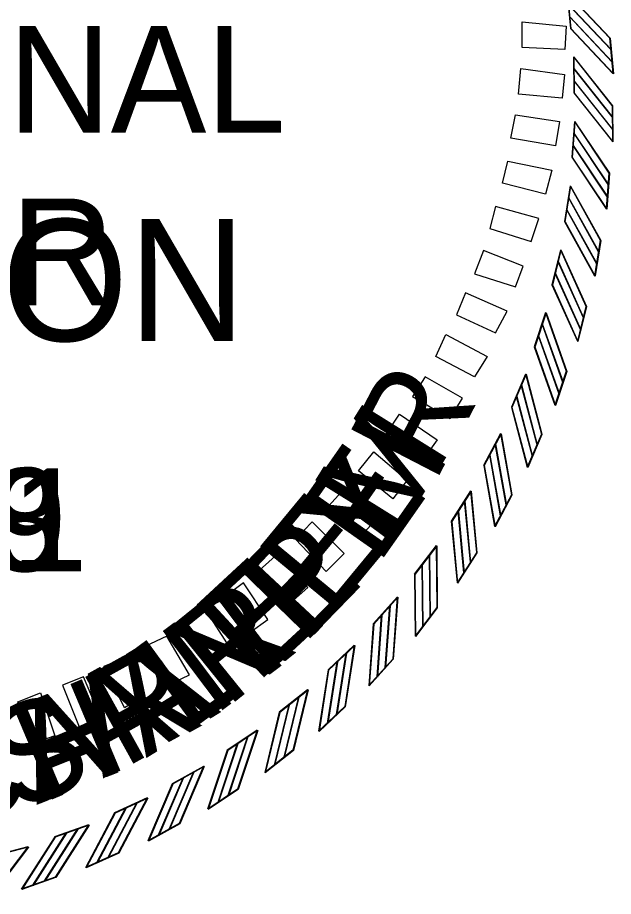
# Model space of a CAD drawing. Extents: x 16 to 1228740, y 11 to 152440.
# Drawn here: x 17.7889 to 17.8514, y 10.8175 to 10.9098 of the extents above; entities that cross this region are included whole.
import ezdxf

# ---------------------------------------------------------------- set-up
doc = ezdxf.new("R2010")
doc.units = 0
for name, color, linetype in [('STAMP_FRED', 7, 'Continuous'), ('STAMP_HUSSAM', 7, 'Continuous'), ('STAMP_JUSTIN', 7, 'Continuous'), ('STAMP_PRELIM', 7, 'Continuous')]:
    doc.layers.add(name, color=color, linetype=linetype)

msp = doc.modelspace()

# ---------------------------------------------------------------- linework, layer by layer
at = {"layer": 'STAMP_FRED'}
for p, q in [((17.84661, 10.912405), (17.846957, 10.908642)), ((17.851077, 10.90765), (17.851423, 10.903896)), ((17.847275, 10.905655), (17.84731, 10.901877)), ((17.851334, 10.900548), (17.851369, 10.896778)), ((17.847381, 10.898874), (17.847104, 10.895106)), ((17.851004, 10.893449), (17.850727, 10.889689)), ((17.846926, 10.892108), (17.846339, 10.888375)), ((17.850089, 10.886402), (17.849503, 10.882678)), ((17.845915, 10.885402), (17.845021, 10.88173)), ((17.844352, 10.878802), (17.843158, 10.875217)), ((17.848595, 10.879454), (17.847704, 10.875791)), ((17.842251, 10.872354), (17.840765, 10.86888)), ((17.846533, 10.872653), (17.845342, 10.869077)), ((17.839623, 10.866102), (17.837856, 10.862762)), ((17.843916, 10.866046), (17.842433, 10.86258)), ((17.836489, 10.860087), (17.834451, 10.856905)), ((17.840762, 10.859678), (17.838999, 10.856346)), ((17.832869, 10.854353), (17.830575, 10.85135)), ((17.837093, 10.853592), (17.835061, 10.850417)), ((17.828787, 10.848937), (17.826253, 10.846133)), ((17.832935, 10.847829), (17.830646, 10.844833)), ((17.824272, 10.843876), (17.821516, 10.841291)), ((17.828314, 10.84243), (17.825786, 10.839633)), ((17.819355, 10.839205), (17.816394, 10.836857)), ((17.823263, 10.83743), (17.820513, 10.834852)), ((17.814068, 10.834957), (17.810924, 10.832861)), ((17.817817, 10.832865), (17.814864, 10.830522)), ((17.808449, 10.831159), (17.805143, 10.829331)), ((17.812013, 10.828765), (17.808876, 10.826674)), ((17.802536, 10.827839), (17.799089, 10.826289)), ((17.796368, 10.825018), (17.792806, 10.823758)), ((17.805889, 10.825159), (17.80259, 10.823334)), ((17.789989, 10.822716), (17.786335, 10.821755)), ((17.799489, 10.82207), (17.796051, 10.820524)), ((17.792855, 10.819521), (17.789301, 10.818264))]:
    msp.add_line(p, q, dxfattribs=at)
for points in [[(17.846606, 10.912409), (17.851073, 10.907655)], [(17.846706, 10.9112), (17.851173, 10.906446)], [(17.846855, 10.909898), (17.851322, 10.905144)], [(17.846959, 10.908647), (17.851426, 10.903893)], [(17.847272, 10.90566), (17.851331, 10.900553)], [(17.847272, 10.904447), (17.851331, 10.89934)], [(17.847313, 10.903137), (17.851372, 10.898031)], [(17.847313, 10.901881), (17.851372, 10.896775)], [(17.847378, 10.898879), (17.851001, 10.893455)], [(17.847278, 10.89767), (17.850901, 10.892245)], [(17.84721, 10.896362), (17.850834, 10.890937)], [(17.847107, 10.89511), (17.85073, 10.889686)], [(17.846924, 10.892113), (17.850087, 10.886408)], [(17.846724, 10.890916), (17.849887, 10.885211)], [(17.846549, 10.889618), (17.849712, 10.883913)], [(17.846342, 10.888379), (17.849505, 10.882674)], [(17.845912, 10.885407), (17.848593, 10.87946)], [(17.845614, 10.884231), (17.848295, 10.878284)], [(17.845333, 10.882951), (17.848014, 10.877005)], [(17.845024, 10.881734), (17.847705, 10.875787)], [(17.84435, 10.878807), (17.846531, 10.87266)], [(17.843956, 10.87766), (17.846137, 10.871512)], [(17.84357, 10.876408), (17.845751, 10.87026)], [(17.843162, 10.87522), (17.845343, 10.869072)], [(17.842249, 10.87236), (17.843915, 10.866053)], [(17.841762, 10.871248), (17.843427, 10.864941)], [(17.841273, 10.870033), (17.842939, 10.863726)], [(17.840769, 10.868883), (17.842434, 10.862576)], [(17.839622, 10.866107), (17.840762, 10.859684)], [(17.839045, 10.86504), (17.840184, 10.858617)], [(17.838458, 10.863869), (17.839597, 10.857446)], [(17.83786, 10.862765), (17.838999, 10.856342)], [(17.836488, 10.860093), (17.837093, 10.853598)], [(17.835825, 10.859077), (17.83643, 10.852582)], [(17.835143, 10.857959), (17.835748, 10.851464)], [(17.834456, 10.856907), (17.835061, 10.850412)], [(17.832869, 10.854358), (17.832935, 10.847836)], [(17.832123, 10.853401), (17.83219, 10.846878)], [(17.831351, 10.852343), (17.831418, 10.84582)], [(17.83058, 10.851351), (17.830646, 10.844829)], [(17.828787, 10.848942), (17.828315, 10.842436)], [(17.827966, 10.84805), (17.827493, 10.841543)], [(17.827109, 10.847059), (17.826637, 10.840552)], [(17.826258, 10.846134), (17.825786, 10.839628)], [(17.824273, 10.843882), (17.823265, 10.837437)], [(17.82338, 10.84306), (17.822372, 10.836615)], [(17.822445, 10.842143), (17.821437, 10.835698)], [(17.821521, 10.841292), (17.820513, 10.834847)], [(17.819356, 10.839211), (17.817819, 10.832871)], [(17.818398, 10.838466), (17.816862, 10.832126)], [(17.81739, 10.837629), (17.815854, 10.83129)], [(17.816399, 10.836858), (17.814862, 10.830518)], [(17.813054, 10.834299), (17.810999, 10.828108)], [(17.81407, 10.834962), (17.812015, 10.828771)], [(17.811981, 10.833548), (17.809926, 10.827357)], [(17.810929, 10.832861), (17.808874, 10.82667)], [(17.807384, 10.830587), (17.804825, 10.824587)], [(17.808452, 10.831165), (17.805892, 10.825165)], [(17.806252, 10.829928), (17.803693, 10.823928)], [(17.805148, 10.82933), (17.802589, 10.82333)], [(17.802538, 10.827844), (17.799492, 10.822076)], [(17.801427, 10.827357), (17.798381, 10.821588)], [(17.799095, 10.826289), (17.796048, 10.82052)], [(17.800245, 10.826793), (17.797199, 10.821025)], [(17.796371, 10.825023), (17.792859, 10.819526)], [(17.793999, 10.824165), (17.790487, 10.818668)], [(17.795224, 10.824629), (17.791712, 10.819132)], [(17.792811, 10.823757), (17.789299, 10.81826)], [(17.789992, 10.822721), (17.786038, 10.817533)]]:
    msp.add_lwpolyline(points, dxfattribs=at)
at = {"layer": 'STAMP_HUSSAM'}
for p, q in [((17.846554, 10.912435), (17.846901, 10.908673)), ((17.851021, 10.907681), (17.851367, 10.903927)), ((17.847219, 10.905686), (17.847254, 10.901908)), ((17.851278, 10.900579), (17.851313, 10.896809)), ((17.847325, 10.898905), (17.847048, 10.895137)), ((17.850948, 10.89348), (17.850672, 10.88972)), ((17.846871, 10.892138), (17.846283, 10.888406)), ((17.850033, 10.886433), (17.849447, 10.882708)), ((17.845859, 10.885432), (17.844965, 10.881761)), ((17.84854, 10.879485), (17.847648, 10.875822)), ((17.844297, 10.878833), (17.843103, 10.875248)), ((17.842195, 10.872385), (17.840709, 10.868911)), ((17.846477, 10.872684), (17.845286, 10.869107)), ((17.839568, 10.866132), (17.8378, 10.862793)), ((17.84386, 10.866077), (17.842378, 10.862611)), ((17.836433, 10.860118), (17.834396, 10.856936)), ((17.840706, 10.859709), (17.838943, 10.856377)), ((17.832813, 10.854384), (17.830519, 10.85138)), ((17.837038, 10.853622), (17.835005, 10.850448)), ((17.828731, 10.848967), (17.826198, 10.846164)), ((17.832879, 10.84786), (17.830591, 10.844864)), ((17.824216, 10.843907), (17.82146, 10.841322)), ((17.828258, 10.842461), (17.825731, 10.839664)), ((17.819299, 10.839236), (17.816338, 10.836888)), ((17.823208, 10.837461), (17.820458, 10.834883)), ((17.814013, 10.834988), (17.810868, 10.832892)), ((17.817761, 10.832896), (17.814808, 10.830553)), ((17.808393, 10.83119), (17.805087, 10.829361)), ((17.811957, 10.828796), (17.80882, 10.826705)), ((17.80248, 10.82787), (17.799034, 10.82632)), ((17.796313, 10.825049), (17.79275, 10.823789)), ((17.805833, 10.82519), (17.802534, 10.823365)), ((17.789933, 10.822747), (17.786279, 10.821786)), ((17.799433, 10.822101), (17.795995, 10.820555)), ((17.7928, 10.819552), (17.789245, 10.818295))]:
    msp.add_line(p, q, dxfattribs=at)
for points in [[(17.84655, 10.91244), (17.851017, 10.907686)], [(17.84665, 10.91123), (17.851117, 10.906476)], [(17.846799, 10.909929), (17.851266, 10.905175)], [(17.846903, 10.908677), (17.85137, 10.903923)], [(17.847216, 10.905691), (17.851275, 10.900584)], [(17.847216, 10.904477), (17.851275, 10.899371)], [(17.847257, 10.903168), (17.851316, 10.898061)], [(17.847257, 10.901912), (17.851316, 10.896806)], [(17.847322, 10.89891), (17.850945, 10.893486)], [(17.847222, 10.897701), (17.850845, 10.892276)], [(17.847155, 10.896392), (17.850778, 10.890968)], [(17.847051, 10.895141), (17.850674, 10.889716)], [(17.846868, 10.892144), (17.850031, 10.886438)], [(17.846668, 10.890947), (17.849831, 10.885242)], [(17.846493, 10.889648), (17.849656, 10.883943)], [(17.846286, 10.88841), (17.849449, 10.882705)], [(17.845856, 10.885438), (17.848537, 10.879491)], [(17.845559, 10.884261), (17.84824, 10.878315)], [(17.845277, 10.882982), (17.847958, 10.877035)], [(17.844969, 10.881765), (17.84765, 10.875818)], [(17.844295, 10.878838), (17.846476, 10.87269)], [(17.843901, 10.877691), (17.846082, 10.871543)], [(17.843514, 10.876439), (17.845695, 10.870291)], [(17.843107, 10.875251), (17.845287, 10.869103)], [(17.842193, 10.87239), (17.843859, 10.866083)], [(17.841706, 10.871279), (17.843372, 10.864972)], [(17.841218, 10.870064), (17.842883, 10.863757)], [(17.840713, 10.868914), (17.842379, 10.862607)], [(17.839567, 10.866138), (17.840706, 10.859715)], [(17.838989, 10.865071), (17.840128, 10.858648)], [(17.838402, 10.8639), (17.839541, 10.857477)], [(17.837804, 10.862795), (17.838943, 10.856372)], [(17.836433, 10.860124), (17.837038, 10.853629)], [(17.835769, 10.859108), (17.836374, 10.852613)], [(17.835087, 10.85799), (17.835692, 10.851495)], [(17.8344, 10.856938), (17.835005, 10.850443)], [(17.832813, 10.854389), (17.832879, 10.847866)], [(17.832067, 10.853432), (17.832134, 10.846909)], [(17.831296, 10.852373), (17.831362, 10.845851)], [(17.830524, 10.851382), (17.830591, 10.844859)], [(17.82791, 10.84808), (17.827437, 10.841574)], [(17.828732, 10.848973), (17.828259, 10.842467)], [(17.827053, 10.847089), (17.826581, 10.840583)], [(17.826203, 10.846165), (17.82573, 10.839659)], [(17.824217, 10.843912), (17.823209, 10.837468)], [(17.823324, 10.843091), (17.822316, 10.836646)], [(17.822389, 10.842174), (17.821381, 10.835729)], [(17.821465, 10.841323), (17.820457, 10.834878)], [(17.8193, 10.839242), (17.817763, 10.832902)], [(17.818343, 10.838497), (17.816806, 10.832157)], [(17.817335, 10.83766), (17.815798, 10.83132)], [(17.816344, 10.836889), (17.814807, 10.830549)], [(17.812999, 10.83433), (17.810943, 10.828139)], [(17.814014, 10.834993), (17.811959, 10.828802)], [(17.811925, 10.833579), (17.80987, 10.827388)], [(17.810873, 10.832892), (17.808818, 10.826701)], [(17.807329, 10.830618), (17.804769, 10.824618)], [(17.808396, 10.831196), (17.805836, 10.825195)], [(17.806197, 10.829959), (17.803637, 10.823959)], [(17.805092, 10.829361), (17.802533, 10.823361)], [(17.802483, 10.827875), (17.799437, 10.822107)], [(17.801371, 10.827388), (17.798325, 10.821619)], [(17.799039, 10.82632), (17.795993, 10.820551)], [(17.800189, 10.826824), (17.797143, 10.821056)], [(17.796316, 10.825054), (17.792804, 10.819557)], [(17.793943, 10.824196), (17.790431, 10.818699)], [(17.795168, 10.82466), (17.791656, 10.819163)], [(17.792755, 10.823788), (17.789243, 10.818291)], [(17.789937, 10.822752), (17.785983, 10.817564)]]:
    msp.add_lwpolyline(points, dxfattribs=at)
at = {"layer": 'STAMP_JUSTIN'}
for p, q in [((17.846608, 10.912405), (17.846954, 10.908643)), ((17.851075, 10.907651), (17.85142, 10.903897)), ((17.847273, 10.905656), (17.847308, 10.901878)), ((17.851332, 10.900549), (17.851367, 10.896779)), ((17.847379, 10.898875), (17.847102, 10.895107)), ((17.851002, 10.89345), (17.850725, 10.889691)), ((17.846924, 10.892109), (17.846337, 10.888376)), ((17.850087, 10.886403), (17.849501, 10.882679)), ((17.845912, 10.885403), (17.845019, 10.881732)), ((17.848593, 10.879455), (17.847701, 10.875793)), ((17.84435, 10.878804), (17.843156, 10.875219)), ((17.842249, 10.872356), (17.840763, 10.868881)), ((17.846531, 10.872655), (17.84534, 10.869078)), ((17.839622, 10.866103), (17.837854, 10.862764)), ((17.843914, 10.866048), (17.842431, 10.862582)), ((17.836487, 10.860089), (17.83445, 10.856907)), ((17.84076, 10.85968), (17.838997, 10.856348)), ((17.832867, 10.854355), (17.830574, 10.851352)), ((17.837092, 10.853594), (17.835059, 10.850419)), ((17.828785, 10.848939), (17.826252, 10.846135)), ((17.832933, 10.847831), (17.830645, 10.844835)), ((17.824271, 10.843878), (17.821514, 10.841294)), ((17.828312, 10.842432), (17.825785, 10.839635)), ((17.819353, 10.839208), (17.816393, 10.83686)), ((17.823262, 10.837433), (17.820512, 10.834854)), ((17.814067, 10.834959), (17.810923, 10.832864)), ((17.817816, 10.832868), (17.814862, 10.830525)), ((17.808448, 10.831162), (17.805142, 10.829333)), ((17.812011, 10.828768), (17.808874, 10.826677)), ((17.802535, 10.827842), (17.799089, 10.826292)), ((17.796367, 10.825021), (17.792805, 10.823761)), ((17.805888, 10.825162), (17.802589, 10.823337)), ((17.789988, 10.822719), (17.786334, 10.821758)), ((17.799488, 10.822073), (17.79605, 10.820527)), ((17.792855, 10.819524), (17.7893, 10.818267))]:
    msp.add_line(p, q, dxfattribs=at)
for points in [[(17.846604, 10.91241), (17.851071, 10.907656)], [(17.846704, 10.9112), (17.851171, 10.906446)], [(17.846853, 10.909899), (17.85132, 10.905145)], [(17.846957, 10.908647), (17.851423, 10.903893)], [(17.84727, 10.905661), (17.851328, 10.900554)], [(17.84727, 10.904447), (17.851328, 10.899341)], [(17.847311, 10.903138), (17.851369, 10.898032)], [(17.847311, 10.901882), (17.851369, 10.896776)], [(17.847376, 10.89888), (17.850999, 10.893456)], [(17.847276, 10.897671), (17.850899, 10.892247)], [(17.847208, 10.896363), (17.850831, 10.890938)], [(17.847105, 10.895111), (17.850728, 10.889687)], [(17.846922, 10.892114), (17.850084, 10.886409)], [(17.846722, 10.890917), (17.849885, 10.885212)], [(17.846547, 10.889619), (17.84971, 10.883914)], [(17.84634, 10.88838), (17.849503, 10.882675)], [(17.84591, 10.885408), (17.848591, 10.879462)], [(17.845612, 10.884232), (17.848293, 10.878285)], [(17.845331, 10.882953), (17.848012, 10.877006)], [(17.845022, 10.881735), (17.847703, 10.875789)], [(17.844348, 10.878809), (17.846529, 10.872661)], [(17.843954, 10.877661), (17.846135, 10.871514)], [(17.843568, 10.87641), (17.845749, 10.870262)], [(17.84316, 10.875222), (17.845341, 10.869074)], [(17.842247, 10.872361), (17.843913, 10.866054)], [(17.84176, 10.87125), (17.843425, 10.864943)], [(17.841271, 10.870035), (17.842937, 10.863728)], [(17.840767, 10.868884), (17.842433, 10.862578)], [(17.839621, 10.866109), (17.84076, 10.859686)], [(17.839043, 10.865042), (17.840182, 10.858619)], [(17.838456, 10.863871), (17.839595, 10.857448)], [(17.837858, 10.862766), (17.838997, 10.856344)], [(17.836487, 10.860095), (17.837091, 10.8536)], [(17.835823, 10.859079), (17.836428, 10.852584)], [(17.835141, 10.857961), (17.835746, 10.851466)], [(17.834454, 10.856909), (17.835059, 10.850415)], [(17.832867, 10.854361), (17.832933, 10.847838)], [(17.832122, 10.853403), (17.832188, 10.84688)], [(17.83135, 10.852345), (17.831416, 10.845822)], [(17.830578, 10.851354), (17.830645, 10.844831)], [(17.828786, 10.848944), (17.828313, 10.842439)], [(17.827964, 10.848052), (17.827492, 10.841546)], [(17.827107, 10.847061), (17.826635, 10.840555)], [(17.826257, 10.846137), (17.825784, 10.839631)], [(17.824271, 10.843884), (17.823263, 10.837439)], [(17.823379, 10.843062), (17.822371, 10.836617)], [(17.822443, 10.842145), (17.821435, 10.835701)], [(17.821519, 10.841295), (17.820511, 10.83485)], [(17.819355, 10.839213), (17.817818, 10.832874)], [(17.818397, 10.838468), (17.81686, 10.832129)], [(17.817389, 10.837632), (17.815852, 10.831292)], [(17.816398, 10.83686), (17.814861, 10.830521)], [(17.813053, 10.834301), (17.810998, 10.82811)], [(17.814069, 10.834965), (17.812014, 10.828774)], [(17.811979, 10.833551), (17.809924, 10.82736)], [(17.810928, 10.832864), (17.808873, 10.826673)], [(17.807383, 10.83059), (17.804824, 10.82459)], [(17.80845, 10.831167), (17.805891, 10.825167)], [(17.806251, 10.829931), (17.803692, 10.823931)], [(17.805147, 10.829333), (17.802587, 10.823333)], [(17.802537, 10.827847), (17.799491, 10.822079)], [(17.801426, 10.827359), (17.79838, 10.821591)], [(17.799094, 10.826291), (17.796048, 10.820523)], [(17.800244, 10.826796), (17.797198, 10.821028)], [(17.796371, 10.825026), (17.792859, 10.819529)], [(17.793998, 10.824168), (17.790486, 10.818671)], [(17.795223, 10.824632), (17.791711, 10.819135)], [(17.79281, 10.82376), (17.789298, 10.818263)], [(17.789992, 10.822724), (17.786038, 10.817536)]]:
    msp.add_lwpolyline(points, dxfattribs=at)
at = {"layer": 'STAMP_PRELIM'}
for p, q in [((17.841835, 10.90935), (17.84646, 10.908908)), ((17.841835, 10.906658), (17.841835, 10.90935)), ((17.84646, 10.908908), (17.846335, 10.906475)), ((17.846335, 10.906475), (17.841835, 10.906658)), ((17.84146, 10.901783), (17.84171, 10.904475)), ((17.84171, 10.904475), (17.846276, 10.90385)), ((17.846276, 10.90385), (17.846026, 10.90135)), ((17.846026, 10.90135), (17.84146, 10.901783)), ((17.840651, 10.897158), (17.841151, 10.8996)), ((17.841151, 10.8996), (17.845776, 10.898908)), ((17.845776, 10.898908), (17.845335, 10.89635)), ((17.845335, 10.89635), (17.840651, 10.897158)), ((17.839776, 10.892408), (17.840335, 10.894725)), ((17.840335, 10.894725), (17.84496, 10.893783)), ((17.84496, 10.893783), (17.844276, 10.891283)), ((17.844276, 10.891283), (17.839776, 10.892408)), ((17.839026, 10.889975), (17.83846, 10.887658)), ((17.843585, 10.888725), (17.839026, 10.889975)), ((17.842776, 10.886283), (17.843585, 10.888725)), ((17.83846, 10.887658), (17.842776, 10.886283)), ((17.837776, 10.88535), (17.836835, 10.882908)), ((17.84196, 10.883725), (17.837776, 10.88535)), ((17.841151, 10.881533), (17.84196, 10.883725)), ((17.836835, 10.882908), (17.841151, 10.881533)), ((17.835901, 10.880908), (17.83496, 10.8786)), ((17.840276, 10.878975), (17.835901, 10.880908)), ((17.83496, 10.8786), (17.839026, 10.876725)), ((17.839026, 10.876725), (17.840276, 10.878975)), ((17.832776, 10.874225), (17.833835, 10.876533)), ((17.833835, 10.876533), (17.838151, 10.874225)), ((17.836835, 10.8721), (17.832776, 10.874225)), ((17.838151, 10.874225), (17.836835, 10.8721)), ((17.831651, 10.8721), (17.830335, 10.870033)), ((17.835585, 10.86985), (17.831651, 10.8721)), ((17.830335, 10.870033), (17.834276, 10.867725)), ((17.834276, 10.867725), (17.835585, 10.86985)), ((17.827585, 10.8661), (17.82896, 10.868158)), ((17.82896, 10.868158), (17.832901, 10.865475)), ((17.831335, 10.863283), (17.827585, 10.8661)), ((17.832901, 10.865475), (17.831335, 10.863283)), ((17.824651, 10.862225), (17.826276, 10.864225)), ((17.826276, 10.864225), (17.829776, 10.861225)), ((17.828276, 10.859283), (17.824651, 10.862225)), ((17.829776, 10.861225), (17.828276, 10.859283)), ((17.82321, 10.860408), (17.821527, 10.858533)), ((17.826651, 10.857283), (17.82321, 10.860408)), ((17.821527, 10.858533), (17.824901, 10.85535)), ((17.819777, 10.85685), (17.818027, 10.855033)), ((17.823151, 10.853533), (17.819777, 10.85685)), ((17.824901, 10.85535), (17.826651, 10.857283)), ((17.818027, 10.855033), (17.821277, 10.851658)), ((17.81621, 10.853533), (17.814277, 10.851783)), ((17.819335, 10.849975), (17.81621, 10.853533)), ((17.821277, 10.851658), (17.823151, 10.853533)), ((17.814277, 10.851783), (17.817527, 10.84835)), ((17.812585, 10.850475), (17.810527, 10.848908)), ((17.815152, 10.8466), (17.812585, 10.850475)), ((17.817527, 10.84835), (17.819335, 10.849975)), ((17.810527, 10.848908), (17.813277, 10.845283)), ((17.808585, 10.847658), (17.80646, 10.846225)), ((17.811152, 10.843658), (17.808585, 10.847658)), ((17.813277, 10.845283), (17.815152, 10.8466)), ((17.80646, 10.846225), (17.809085, 10.84235)), ((17.804527, 10.84485), (17.80221, 10.843783)), ((17.806902, 10.840783), (17.804527, 10.84485)), ((17.80221, 10.843783), (17.804652, 10.839725)), ((17.809085, 10.84235), (17.811152, 10.843658)), ((17.79796, 10.841725), (17.800277, 10.842658)), ((17.800277, 10.842658), (17.80221, 10.8386)), ((17.800085, 10.83735), (17.79796, 10.841725)), ((17.804652, 10.839725), (17.806902, 10.840783)), ((17.795777, 10.8406), (17.793585, 10.839725)), ((17.797527, 10.836475), (17.795777, 10.8406)), ((17.788902, 10.837975), (17.791277, 10.838908)), ((17.791277, 10.838908), (17.792777, 10.834408)), ((17.793585, 10.839725), (17.795335, 10.83535)), ((17.79046, 10.8336), (17.788902, 10.837975)), ((17.80221, 10.8386), (17.800085, 10.83735)), ((17.795335, 10.83535), (17.797527, 10.836475)), ((17.792777, 10.834408), (17.79046, 10.8336))]:
    msp.add_line(p, q, dxfattribs=at)

# ---------------------------------------------------------------- texts
at = {"layer": 'STAMP_FRED'}
for s, height, p in [('PROFESSIONAL', 0.01119382, (17.700561, 10.897711)), ('ENGINEER', 0.0111938, (17.720817, 10.879588)), ('No.14501', 0.010794, (17.733619, 10.851677))]:
    msp.add_text(s, height=height, dxfattribs=at).set_placement(p)
for s, rotation, p in [('R', 62.64183, (17.832632, 10.860768)), ('E', 54.98102, (17.826674, 10.852207)), ('P', 46.95541, (17.819268, 10.844174)), ('R', 38.92979, (17.810813, 10.837254)), ('A', 31.63379, (17.802356, 10.832043)), ('H', 22.87857, (17.791437, 10.827269))]:
    msp.add_text(s, height=0.010417, rotation=rotation, dxfattribs=at).set_placement(p)
at = {"layer": 'STAMP_HUSSAM'}
for s, height, p in [('PROFESSIONAL', 0.01119382, (17.700506, 10.897742)), ('ENGINEER', 0.0111938, (17.720761, 10.879619)), ('No.18919', 0.010794, (17.731422, 10.851708))]:
    msp.add_text(s, height=height, dxfattribs=at).set_placement(p)
for s, rotation, p in [('M', 58.09407, (17.82835, 10.854758)), ('E', 50.44188, (17.821626, 10.846772)), ('E', 42.78968, (17.813899, 10.839753)), ('L', 36.23065, (17.806581, 10.834601)), ('A', 28.94284, (17.79782, 10.829899)), ('S', 21.65504, (17.788534, 10.826346))]:
    msp.add_text(s, height=0.010417, rotation=rotation, dxfattribs=at).set_placement(p)
at = {"layer": 'STAMP_JUSTIN'}
for s, height, p in [('PROFESSIONAL', 0.01119355, (17.700563, 10.897712)), ('ENGINEER', 0.0111936, (17.720818, 10.879589)), ('No.18018', 0.0107938, (17.731051, 10.851679))]:
    msp.add_text(s, height=height, dxfattribs=at).set_placement(p)
for s, rotation, p in [('Y', 53.44327, (17.825933, 10.851388)), ('E', 45.78246, (17.818785, 10.843803)), ('N', 37.02725, (17.809464, 10.836392)), ('R', 29.00164, (17.800018, 10.830917)), ('A', 21.70563, (17.790843, 10.827128)), ('C', 14.04482, (17.780774, 10.824438))]:
    msp.add_text(s, height=0.010416, rotation=rotation, dxfattribs=at).set_placement(p)
at = {"layer": 'STAMP_PRELIM'}
msp.add_text('REVISION', height=0.0127938, dxfattribs=at).set_placement((17.731085, 10.87585))

doc.saveas('drawing.dxf')
